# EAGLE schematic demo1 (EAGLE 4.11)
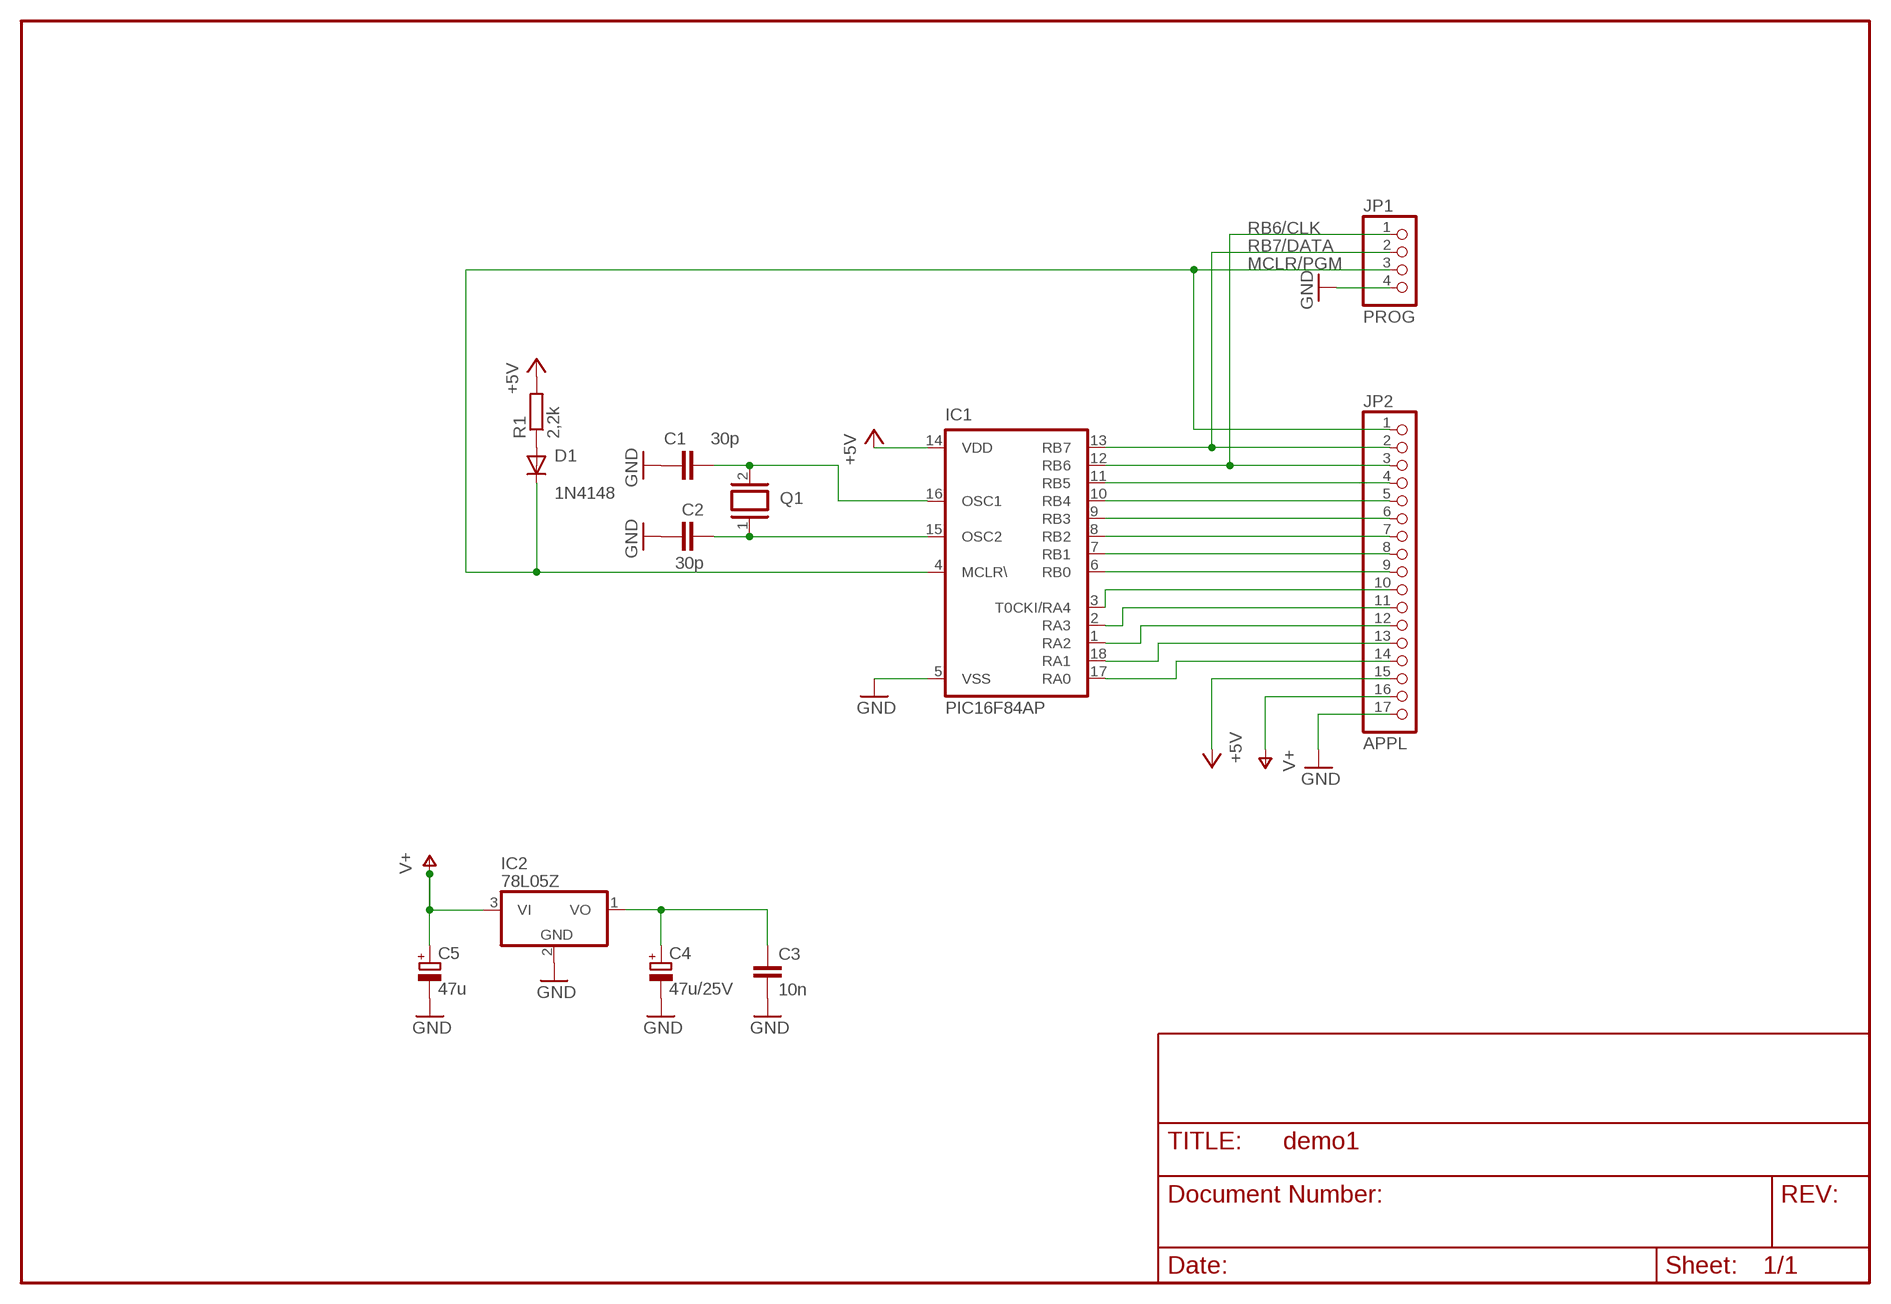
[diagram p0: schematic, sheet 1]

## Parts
C1  30p  C-EUC1206  [C1206]
C2  30p  C-EUC1206  [C1206]
C3  10n  C-EU025-025X050  [C025-025X050]
C4  47u/25V  CPOL-EUTAP5-45  [TAP5-45]
C5  47u  CPOL-EUTAP5-45  [TAP5-45]
D1  1N4148  [DO35-10]
IC1  PIC16F84AP  [DIL18]
IC2  78L05Z  [TO92]
JP1  PROG  PINHD-1X4  [1X04]
JP2  APPL  PINHD-1X17  [1X17]
Q1  XTAL/S  [QS]
R1  2,2k  R-EU_R1206  [R1206]

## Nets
+5V [power]: IC1.14(VDD) JP2.15 R1.1
GND [power]: C1.1 C2.1 C3.2 C4.- C5.- IC1.5(VSS) IC2.2(GND) JP1.4 JP2.17
MCLR/PGM: D1.C IC1.4(MCLR\) JP1.3 JP2.1
N$1: C3.1 C4.+ IC2.1(VO)
N$2: C1.2 IC1.16(OSC1) Q1.2
N$3: C2.2 IC1.15(OSC2) Q1.1
N$4: D1.A R1.2
RA0: IC1.17(RA0) JP2.14
RA1: IC1.18(RA1) JP2.13
RA2: IC1.1(RA2) JP2.12
RA3: IC1.2(RA3) JP2.11
RA4: IC1.3(T0CKI/RA4) JP2.10
RB0: IC1.6(RB0) JP2.9
RB1: IC1.7(RB1) JP2.8
RB2: IC1.8(RB2) JP2.7
RB3: IC1.9(RB3) JP2.6
RB4: IC1.10(RB4) JP2.5
RB5: IC1.11(RB5) JP2.4
RB6/CLK: IC1.12(RB6) JP1.1 JP2.3
RB7/DATA: IC1.13(RB7) JP1.2 JP2.2
V+ [power]: C5.+ IC2.3(VI) JP2.16

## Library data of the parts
C1-C3 = rcl:C-EU: CAPACITOR, European symbol
C4 C5 = rcl:CPOL-EU: POLARIZED CAPACITOR, European symbol
D1 = diode:1N4148: DIODE
IC1 = microchip:PIC16F8*: MICROCONTROLLER 8-Bit PIC16F8X Family - CMOS Flash/EEPROM Pin Compatible : PIC16F83, PIC16CR83, PIC16F84A, PIC16CR84 see also PIC16C*
IC2 = linear:78*: Positive VOLTAGE REGULATOR
JP1 = pinhead:PINHD-1X4: PIN HEADER
JP2 = pinhead:PINHD-1X17: PIN HEADER
Q1 = special:XTAL/S: CRYSTAL
R1 = rcl:R-EU_: RESISTOR, European symbol

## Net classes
0 default: width 0.3 mm, drill 0.2 mm, clearance 0.6 mm
1 power: width 0.4 mm, drill 0.2 mm, clearance 0.6 mm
